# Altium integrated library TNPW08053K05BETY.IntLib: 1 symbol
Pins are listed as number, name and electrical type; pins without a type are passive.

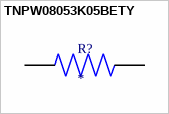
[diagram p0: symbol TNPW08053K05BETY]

## TNPW08053K05BETY
designator R?
MP: TNPW08053K05BETY
footprint RESC2012X55N
pins: 1, 2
